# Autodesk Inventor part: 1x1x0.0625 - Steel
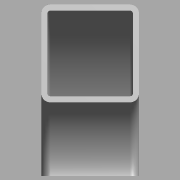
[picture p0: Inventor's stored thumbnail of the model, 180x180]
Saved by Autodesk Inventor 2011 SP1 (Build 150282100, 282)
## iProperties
Created: 2011-03
Part Number: 1x1x0.0625 - Steel
Material: Default
Document SubType Name: Modeling
Designer: bamfomg
Density: 1 g/cm^3
Author: bamfomg
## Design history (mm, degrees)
derived "Square Tube Corners.ipt" dims "d2" = 12.7, "d3" = 12.7, "d6" = 1.5875, "d7" = 1.5875, "d8" = 1.5875, "d12" = 90 deg, "d16" = 1.5875, "d18" = 30 deg, "ID_Rad" = 0.79375, "OD_Rad" = 2.38125, "Side_One" = 25.4, "Side_Two" = 25.4, "Thickness" = 1.5875, "Bend_IDRad" = 19.05, "Bevel_Angl" = 30 deg, "Bevel_Dist" = 1.5875
body "Solid1"
feature "Solid1::Square Tube Corners.ipt" dims "d2" = 12.7, "d3" = 12.7, "d6" = 1.5875, "d7" = 1.5875, "d8" = 1.5875, "d12" = 90 deg, "d16" = 1.5875, "d18" = 30 deg, "ID_Rad" = 0.79375, "OD_Rad" = 2.38125, "Side_One" = 25.4, "Side_Two" = 25.4, "Thickness" = 1.5875, "Bend_IDRad" = 19.05, "Bevel_Angl" = 30 deg, "Bevel_Dist" = 1.5875, "ScaleForDerivedMember" = 10
tag "TaggingFeature1"
